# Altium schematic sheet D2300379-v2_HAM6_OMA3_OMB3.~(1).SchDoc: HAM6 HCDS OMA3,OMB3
size C; Engineer: L. Sanchez; Organization: LIGO Laboratory; Address1: California Institute of Technology; Address2: Massachusetts Institute of Technology; DocumentNumber: D2300379; Revision: v2; SheetNumber: 4; SheetTotal: 9
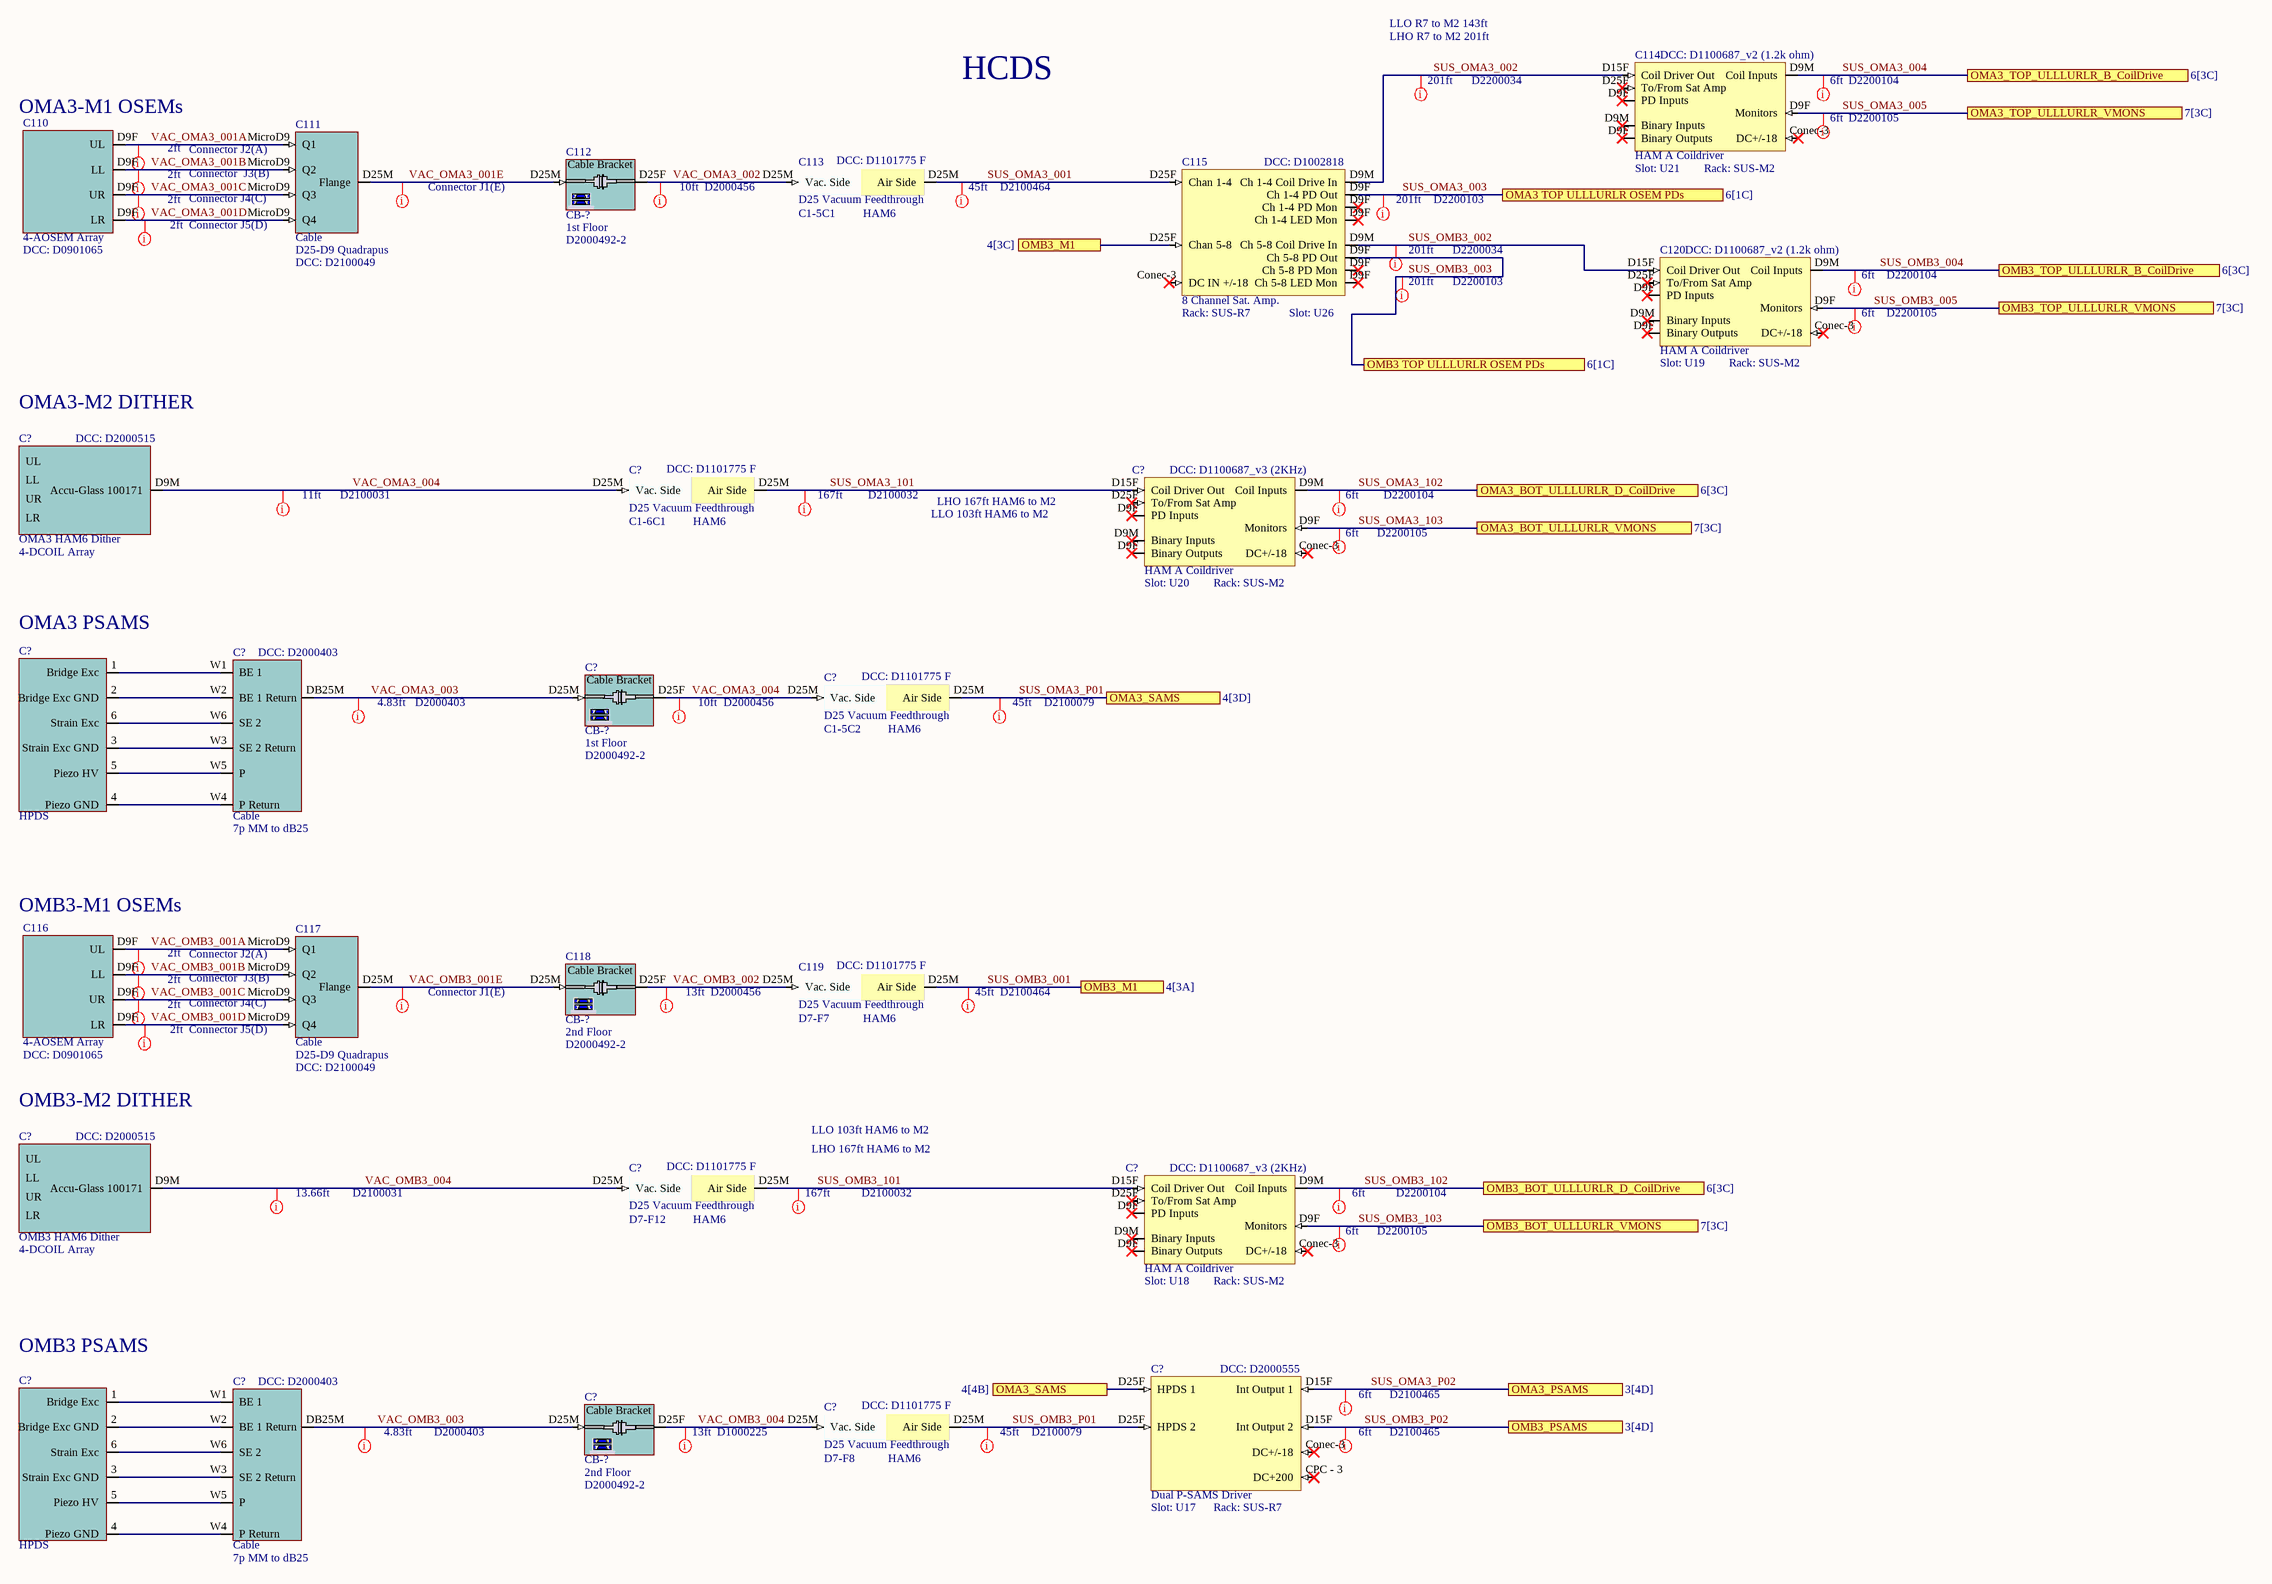
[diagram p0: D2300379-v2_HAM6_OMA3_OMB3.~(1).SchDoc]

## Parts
(Parts that share a designator on the sheet are numbered #1, #2 ... from top to bottom, then left to right.)
C110  4-AOSEM Array  DCC: D0901065
C111  Cable  value D25-D9 Quadrapus  DCC: D2100049
C112  Rack: CB-?  Slot: 1st Floor  DCC: D2000492-2  (hidden comment: Cable Bracket)
C113  D25 Vacuum Feedthrough  DCC: D1101775 F  Feedthrough: C1-5C1  Chamber: HAM6
C114  HAM A Coildriver  DCC: D1100687_v2 (1.2k ohm)  Rack: SUS-M2  Slot: U21
C115  8 Channel Sat. Amp.  DCC: D1002818  Rack: SUS-R7  Slot: U26
C116  4-AOSEM Array  DCC: D0901065
C117  Cable  value D25-D9 Quadrapus  DCC: D2100049
C118  Rack: CB-?  Slot: 2nd Floor  DCC: D2000492-2  (hidden comment: Cable Bracket)
C119  D25 Vacuum Feedthrough  DCC: D1101775 F  Feedthrough: D7-F7  Chamber: HAM6
C120  HAM A Coildriver  DCC: D1100687_v2 (1.2k ohm)  Rack: SUS-M2  Slot: U19
C?#1  value 4-DCOIL Array  Rack: OMA3 HAM6 Dither  DCC: D2000515  (hidden comment: Cable)
C?#2  D25 Vacuum Feedthrough  DCC: D1101775 F  Feedthrough: C1-6C1  Chamber: HAM6
C?#3  HAM A Coildriver  DCC: D1100687_v3 (2KHz)  Rack: SUS-M2  Slot: U20
C?#4  Rack: CB-?  Slot: 1st Floor  DCC: D2000492-2  (hidden comment: Cable Bracket)
C?#5  D25 Vacuum Feedthrough  DCC: D1101775 F  Feedthrough: C1-5C2  Chamber: HAM6
C?#6  Cable  value 7p MM to dB25  DCC: D2000403
C?#7  HPDS
C?#8  value 4-DCOIL Array  Rack: OMB3 HAM6 Dither  DCC: D2000515  (hidden comment: Cable)
C?#9  D25 Vacuum Feedthrough  DCC: D1101775 F  Feedthrough: D7-F12  Chamber: HAM6
C?#10  HAM A Coildriver  DCC: D1100687_v3 (2KHz)  Rack: SUS-M2  Slot: U18
C?#11  Rack: CB-?  Slot: 2nd Floor  DCC: D2000492-2  (hidden comment: Cable Bracket)
C?#12  D25 Vacuum Feedthrough  DCC: D1101775 F  Feedthrough: D7-F8  Chamber: HAM6
C?#13  Dual P-SAMS Driver  Slot: U17  Rack: SUS-R7  DCC: D2000555
C?#14  Cable  value 7p MM to dB25  DCC: D2000403
C?#15  HPDS

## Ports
OMA3 TOP ULLLURLR OSEM PDs (see 6[1C]), OMA3_BOT_ULLLURLR_D_CoilDrive (see 6[3C]), OMA3_BOT_ULLLURLR_VMONS (see 7[3C]), OMA3_PSAMS (see 3[4D]), OMA3_SAMS (see 4[3D]), OMA3_SAMS (see 4[4B]), OMA3_TOP_ULLLURLR_B_CoilDrive (see 6[3C]), OMA3_TOP_ULLLURLR_VMONS (see 7[3C]), OMB3 TOP ULLLURLR OSEM PDs (see 6[1C]), OMB3_BOT_ULLLURLR_D_CoilDrive (see 6[3C]), OMB3_BOT_ULLLURLR_VMONS (see 7[3C]), OMB3_M1 (see 4[3A]), OMB3_M1 (see 4[3C]), OMB3_PSAMS (see 3[4D]), OMB3_TOP_ULLLURLR_B_CoilDrive (see 6[3C]), OMB3_TOP_ULLLURLR_VMONS (see 7[3C])

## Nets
SUS_OMA3_001: C113.D25M(Air_Side) C115.D25F(Chan_1-4)
SUS_OMA3_002: C114.D15F(Coil_Driver_Out) C115.D9M(Ch_1-4_Coil_Drive_In)
SUS_OMA3_003: C115.D9F(Ch_1-4_PD_Out) ; port OMA3 TOP ULLLURLR OSEM PDs
SUS_OMA3_004: C114.D9M(Coil_Inputs) ; port OMA3_TOP_ULLLURLR_B_CoilDrive
SUS_OMA3_005: C114.D9F(PD_Inputs) ; port OMA3_TOP_ULLLURLR_VMONS
SUS_OMA3_101: C?#2.D25M(Air_Side) C?#3.D15F(Coil_Driver_Out)
SUS_OMA3_102: C?#3.D9M(Coil_Inputs) ; port OMA3_BOT_ULLLURLR_D_CoilDrive
SUS_OMA3_103: C?#3.D9F(PD_Inputs) ; port OMA3_BOT_ULLLURLR_VMONS
SUS_OMA3_P01: C?#5.D25M(Air_Side) C?#13.D25F(HPDS_1) ; port OMA3_SAMS
SUS_OMA3_P02: C?#13.D15F(Int_Output_1) ; port OMA3_PSAMS
SUS_OMB3_001: C115.D25F(Chan_5-8) C119.D25M(Air_Side) ; port OMB3_M1
SUS_OMB3_002: C115.D9M(Ch_5-8_Coil_Drive_In) C120.D15F(Coil_Driver_Out)
SUS_OMB3_003: C115.D9F(Ch_5-8_PD_Out) ; port OMB3 TOP ULLLURLR OSEM PDs
SUS_OMB3_004: C120.D9M(Coil_Inputs) ; port OMB3_TOP_ULLLURLR_B_CoilDrive
SUS_OMB3_005: C120.D9F(PD_Inputs) ; port OMB3_TOP_ULLLURLR_VMONS
SUS_OMB3_101: C?#9.D25M(Air_Side) C?#10.D15F(Coil_Driver_Out)
SUS_OMB3_102: C?#10.D9M(Coil_Inputs) ; port OMB3_BOT_ULLLURLR_D_CoilDrive
SUS_OMB3_103: C?#10.D9F(PD_Inputs) ; port OMB3_BOT_ULLLURLR_VMONS
SUS_OMB3_P01: C?#12.D25M(Air_Side) C?#13.D25F(HPDS_2)
SUS_OMB3_P02: C?#13.D15F(Int_Output_2) ; port OMB3_PSAMS
VAC_OMA3_001A: C110.D9F(UL) C111.MicroD9(Q1)
VAC_OMA3_001B: C110.D9F(LL) C111.MicroD9(Q2)
VAC_OMA3_001C: C110.D9F(UR) C111.MicroD9(Q3)
VAC_OMA3_001D: C110.D9F(LR) C111.MicroD9(Q4)
VAC_OMA3_001E: C111.D25M(Flange) C112.D25M
VAC_OMA3_002: C112.D25F C113.D25M(Vac._Side)
VAC_OMA3_003: C?#4.D25M C?#6.DB25M
VAC_OMA3_004: C?#1.D9M(Accu-Glass_100171) C?#2.D25M(Vac._Side) C?#4.D25F C?#5.D25M(Vac._Side)
VAC_OMB3_001A: C116.D9F(UL) C117.MicroD9(Q1)
VAC_OMB3_001B: C116.D9F(LL) C117.MicroD9(Q2)
VAC_OMB3_001C: C116.D9F(UR) C117.MicroD9(Q3)
VAC_OMB3_001D: C116.D9F(LR) C117.MicroD9(Q4)
VAC_OMB3_001E: C117.D25M(Flange) C118.D25M
VAC_OMB3_002: C118.D25F C119.D25M(Vac._Side)
VAC_OMB3_003: C?#11.D25M C?#14.DB25M
VAC_OMB3_004: C?#8.D9M(Accu-Glass_100171) C?#9.D25M(Vac._Side) C?#11.D25F C?#12.D25M(Vac._Side)
NetC?#6_W1: C?#6.W1(BE_1) C?#7.1(Bridge_Exc)
NetC?#6_W2: C?#6.W2(BE_1_Return) C?#7.2(Bridge_Exc_GND)
NetC?#6_W3: C?#6.W3(SE_2_Return) C?#7.3(Strain_Exc_GND)
NetC?#6_W4: C?#6.W4(P_Return) C?#7.4(Piezo_GND)
NetC?#6_W5: C?#6.W5(P) C?#7.5(Piezo_HV)
NetC?#6_W6: C?#6.W6(SE_2) C?#7.6(Strain_Exc)
NetC?#14_W1: C?#14.W1(BE_1) C?#15.1(Bridge_Exc)
NetC?#14_W2: C?#14.W2(BE_1_Return) C?#15.2(Bridge_Exc_GND)
NetC?#14_W3: C?#14.W3(SE_2_Return) C?#15.3(Strain_Exc_GND)
NetC?#14_W4: C?#14.W4(P_Return) C?#15.4(Piezo_GND)
NetC?#14_W5: C?#14.W5(P) C?#15.5(Piezo_HV)
NetC?#14_W6: C?#14.W6(SE_2) C?#15.6(Strain_Exc)

Not connected (* = marked no-connect by the designer): C114 Conec-3(DC+/-18)* D25F(To/From_Sat_Amp)*; C115 Conec-3(DC_IN_+/-18)*; C120 Conec-3(DC+/-18)* D25F(To/From_Sat_Amp)*; C?#3 Conec-3(DC+/-18)* D25F(To/From_Sat_Amp)*; C?#10 Conec-3(DC+/-18)* D25F(To/From_Sat_Amp)*; C?#13 Conec-3(DC+/-18)* CPC - 3(DC+200)*

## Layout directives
Length: 2ft; DCC: Connector J5(D): VAC_OMA3_001D, VAC_OMB3_001D
Length: 2ft; DCC: Connector J2(A): VAC_OMA3_001A, VAC_OMB3_001A
Length: 2ft; DCC: Connector  J3(B): VAC_OMA3_001B, VAC_OMB3_001B
Length: 2ft; DCC: Connector J4(C): VAC_OMA3_001C, VAC_OMB3_001C
Length: 201ft; DCC: D2200034: SUS_OMA3_002, SUS_OMB3_002
Length: 201ft; DCC: D2200103: SUS_OMA3_003, SUS_OMB3_003
Length: 13ft; DCC: D2000456: VAC_OMB3_002
Length: 10ft; DCC: D2000456: VAC_OMA3_002, VAC_OMA3_004
Length: 5; DCC: Connector J1(E): VAC_OMA3_001E, VAC_OMB3_001E
Length: 6ft; DCC: D2200104: SUS_OMA3_004, SUS_OMA3_102, SUS_OMB3_004, SUS_OMB3_102
Length: 6ft; DCC: D2200105: SUS_OMA3_005, SUS_OMA3_103, SUS_OMB3_005, SUS_OMB3_103
Length: 45ft; DCC: D2100464: SUS_OMA3_001, SUS_OMB3_001
Length: 45ft; DCC: D2100079: SUS_OMA3_P01, SUS_OMB3_P01
Length: 4.83ft; DCC: D2000403: VAC_OMA3_003, VAC_OMB3_003
Length: 13ft; DCC: D1000225: VAC_OMB3_004
Length: 6ft; DCC: D2100465: SUS_OMA3_P02, SUS_OMB3_P02
Length: 13.66ft; DCC: D2100031: VAC_OMB3_004
Length: 11ft; DCC: D2100031: VAC_OMA3_004
Length: 167ft; DCC: D2100032: SUS_OMA3_101, SUS_OMB3_101

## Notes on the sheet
- LLO R7 to M2 143ft
- LHO R7 to M2 201ft
- (near C110) OMA3-M1 OSEMs
- HCDS
- OMA3-M2 DITHER
- LLO 103ft HAM6 to M2
- LHO 167ft HAM6 to M2
- (near C?#7) OMA3 PSAMS
- (near C116) OMB3-M1 OSEMs
- OMB3-M2 DITHER
- (near C?#15) OMB3 PSAMS

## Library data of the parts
C110 = 4-BOSEM Array: Rack: SUS-R?; Serial: Sxxxxxxx; Slot: U?; System: SUS; Parameter: OMA1 HAM6 M1
C111 C117 = Flange: Rack: SUS-R?; Serial: Sxxxxxxx; Slot: U?; System: SUS
C112 C?#4 = D1001347-2 1st Cable Bracket: D1001347-2 1/2 Cable Bracket for BSC Tables; Serial: Sxxxxxxx; System: SUS
C113 C119 C?#2 C?#5 C?#9 C?#12 = VacFeedD25: Serial: Sxxxxxxx; System: ISC; Rack: R?; Slot: U?
C114 C120 C?#3 C?#10 = HAM A Coildriver: Serial: Sxxxxxxx; System: ISC
C115 = 8 Channel Sat. Amp.: Serial: Sxxxxxxx; System: ISC
C116 = 4-BOSEM Array: Rack: SUS-R?; Serial: Sxxxxxxx; Slot: U?; System: SUS; Parameter: OMB1 HAM6 M1
C118 C?#11 = D1001347-2 2nd Cable Bracket: D1001347-2 2/2 Cable Bracket for BSC Tables; Serial: Sxxxxxxx; System: SUS
C?#1 C?#8 = COSEM Array: Serial: Sxxxxxxx; Slot: U?; System: SUS
C?#6 C?#14 = MM Piezo: Piezo or Thermal; Rack: SUS-R?; Serial: Sxxxxxxx; Slot?: U?; System: SUS
C?#7 C?#15 = HDS+Piezo: HAM Double Suspension with Piezo Driver
C?#13 = Dual P-SAMS: Strain Gauge and PZT Driver; Serial: Sxxxxxxx; System: SUS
